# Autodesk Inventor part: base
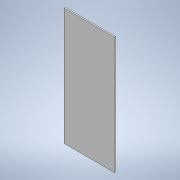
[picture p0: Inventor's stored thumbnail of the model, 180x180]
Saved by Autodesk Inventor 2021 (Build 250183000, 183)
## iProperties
Created: 2026-10
Part Number: base
Material: Generic
Document SubType Name: Modeling
Designer: alolo
Density: 1 g/cm^3
Appearance: Default
Author: alolo
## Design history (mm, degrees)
sketch "Sketch1"
  geometry: L1 (0, 0)-(200, 0); L2 (200, 0)-(200, 465); L3 (200, 465)-(0, 465); L4 (0, 465)-(0, 0)
  constraints: 8 end point, 2 parallel, 1 horizontal, 1 perpendicular
  dimensions: "d0" = 200 distance of L3.end L2.end; "d1" = 465 distance of L2.end L1.end
extrude "Extrusion1" new body sketch "Sketch1" distance "d2" = 5 (= wood_thickness); taper "d3" = 0 deg
body "Solid1"
other parameters: "slide_length" = 195 [user parameter], "slide_angle" = 7 deg [user parameter], "slide_width" = 65 [user parameter], "wood_thickness" = 5 [user parameter; used in 1 equation term], "aclyric_thickness" = 6 [user parameter]
